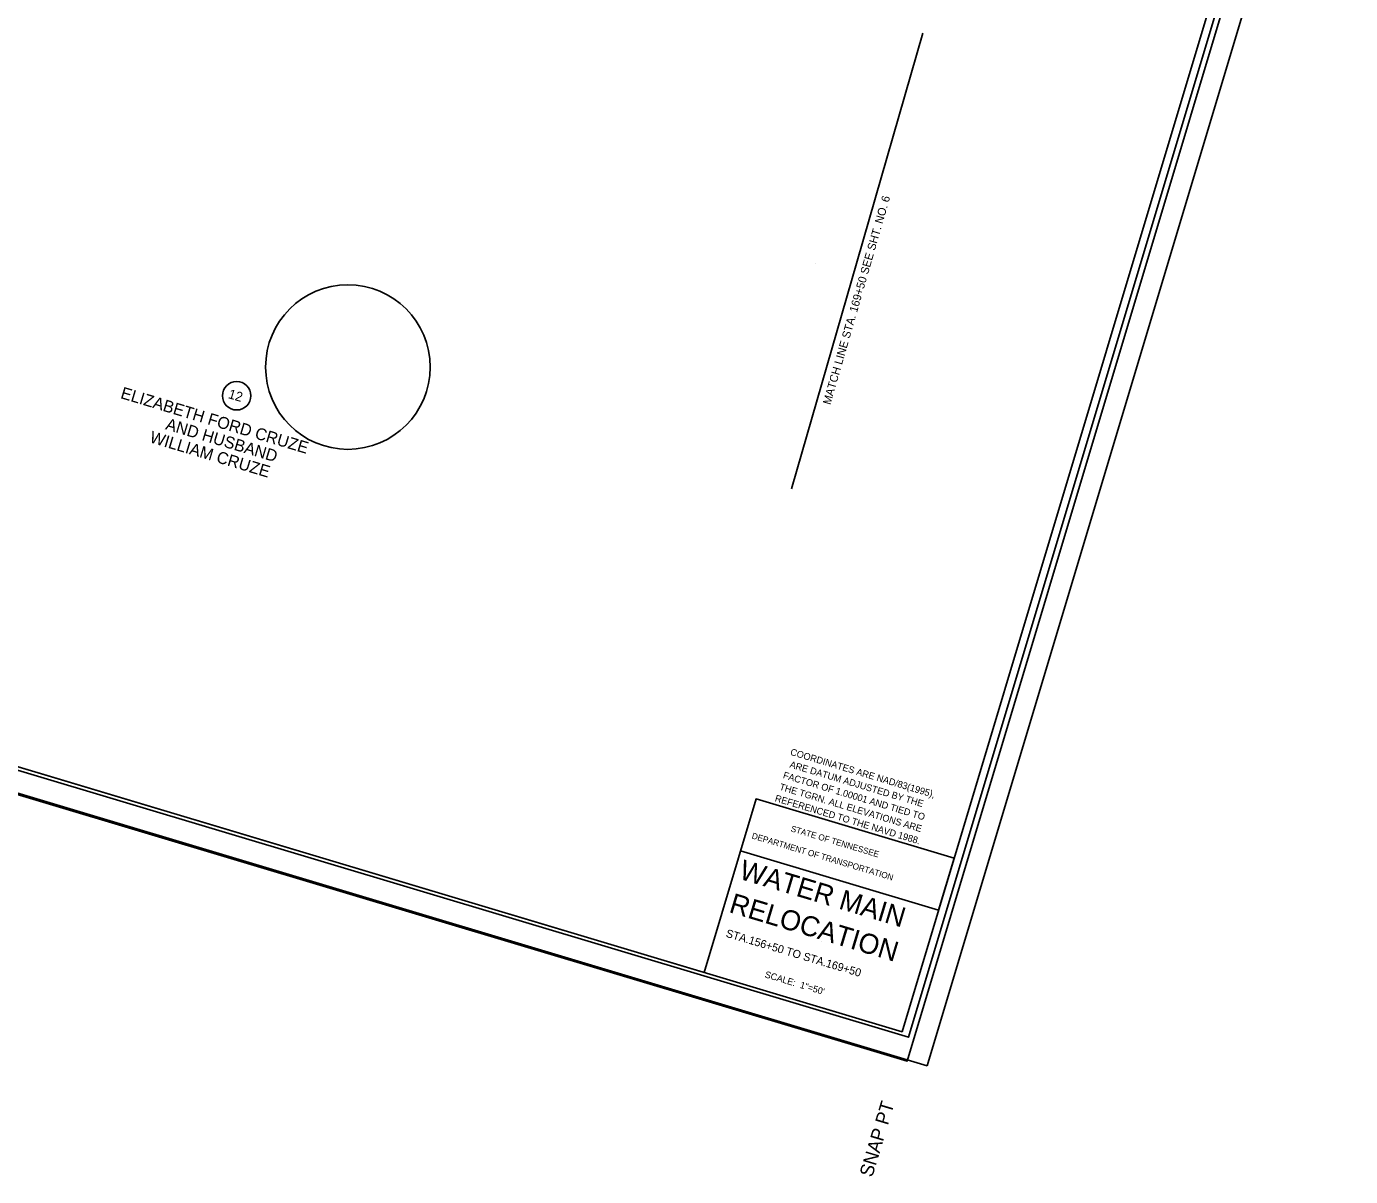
# Model space of a CAD drawing. Extents: x 2627582 to 2629622, y 568931 to 570612.
# Drawn here: x 2628642 to 2629619, y 568931 to 569779 of the extents above; entities that cross this region are included whole.
import ezdxf

# ---------------------------------------------------------------- set-up
doc = ezdxf.new("R2010")
doc.units = 0
for name, color, linetype in [('DESIGN - CENTERLINE - Proposed Text', 7, 'Continuous'), ('DESIGN - SCRATCH - User 1', 7, 'Continuous'), ('DESIGN - SHEET - Corner Text', 7, 'Continuous'), ('DESIGN - SHEET - Light Grid', 7, 'Continuous'), ('DESIGN - SHEET - Linework', 7, 'Continuous'), ('DESIGN - SHEET - Plot Shape', 7, 'Continuous'), ('SURVEY - PROJECT INFORMATION and NOTES', 7, 'Continuous'), ('SURVEY - PROPERTY - Owners', 7, 'Continuous'), ('SURVEY - PROPERTY - Tract Numbers', 7, 'Continuous')]:
    doc.layers.add(name, color=color, linetype=linetype)

msp = doc.modelspace()

# ---------------------------------------------------------------- linework, layer by layer
at = {"layer": 'DESIGN - CENTERLINE - Proposed Text'}
msp.add_lwpolyline([(2629206.17, 569438.02), (2629254.54, 569606.2), (2629302.91, 569774.39)], dxfattribs=at)
at = {"layer": 'DESIGN - SCRATCH - User 1'}
for p, q in [((2629223.72, 569604.66), (2629223.72, 569604.66)), ((2629228.13, 569104.12), (2629228.13, 569104.12))]:
    msp.add_line(p, q, dxfattribs=at)
at = {"layer": 'DESIGN - SHEET - Light Grid'}
msp.add_lwpolyline([(2627697.64, 569511.43), (2629292.52, 569033.35), (2629595.46, 570043.92), (2628000.57, 570522.01)], close=True, dxfattribs=at)
at = {"layer": 'DESIGN - SHEET - Linework'}
for p in [(2629618.55, 570053.91), (2627582.11, 569529.15)]:
    msp.add_line(p, (2629306.31, 569012.3), dxfattribs=at)
for points in [[(2628081.32, 570495.19), (2627779.83, 569489.41), (2629287.73, 569037.39), (2629589.23, 570043.18), (2628081.32, 570495.19)], [(2629141.66, 569081.18), (2629180.03, 569209.2), (2629326.11, 569165.42), (2629314.62, 569127.1), (2629168.55, 569170.89)]]:
    msp.add_lwpolyline(points, dxfattribs=at)
at = {"layer": 'DESIGN - SHEET - Plot Shape'}
for points in [[(2627975.91, 570547.35), (2629604.32, 570059.22), (2629291.51, 569015.7), (2627663.1, 569503.83)], [(2627999.85, 570519.61), (2629589.23, 570043.18), (2629287.73, 569037.39), (2627698.36, 569513.83)]]:
    msp.add_lwpolyline(points, close=True, dxfattribs=at)
at = {"layer": 'SURVEY - PROJECT INFORMATION and NOTES'}
msp.add_circle((2628878.84, 569527.91), 60.7, dxfattribs=at)
at = {"layer": 'SURVEY - PROPERTY - Tract Numbers'}
msp.add_circle((2628796.81, 569506.74), 10.5, dxfattribs=at)

# ---------------------------------------------------------------- texts
at = {"layer": 'DESIGN - CENTERLINE - Proposed Text'}
msp.add_text('MATCH LINE STA. 169+50 SEE SHT. NO. 6', height=6, rotation=73.95539, dxfattribs=at).set_placement((2629234.84, 569499.71))
at = {"layer": 'DESIGN - SHEET - Corner Text'}
for s, height, rotation, p in [('COORDINATES ARE NAD/83(1995),', 5.0001, 343.31329, (2629204.81, 569241.81)), ('ARE DATUM ADJUSTED BY THE', 5.0001, 343.31329, (2629204.38, 569232.55)), ('THE TGRN. ALL ELEVATIONS ARE', 5.0001, 343.31329, (2629196.82, 569216.02)), ('FACTOR OF 1.00001 AND TIED TO', 5.0001, 343.31329, (2629199.47, 569224.62)), ('REFERENCED TO THE NAVD 1988.', 5.0001, 343.31329, (2629193.49, 569207.62)), ('DEPARTMENT OF TRANSPORTATION', 4.5, 343.31329, (2629176.43, 569180.11)), ('STATE OF TENNESSEE', 4.5, 343.31329, (2629205.25, 569185.36)), ('WATER MAIN ', 14.7636, 343.31329, (2629166.72, 569150.47)), ('RELOCATION', 14.764, 343.31329, (2629159.32, 569125.79)), ('STA.156+50 TO STA.169+50', 5.9055, 343.31329, (2629157.26, 569107.55)), ('SCALE:  1"=50\'', 4.9215, 343.31329, (2629186.02, 569077.6)), ('SNAP PT  ', 10, 73.31329, (2629265.67, 568929.49))]:
    msp.add_text(s, height=height, rotation=rotation, dxfattribs=at).set_placement(p)
at = {"layer": 'SURVEY - PROPERTY - Owners'}
for s, p in [('ELIZABETH FORD CRUZE', (2628710.57, 569505.09)), ('AND HUSBAND', (2628743.75, 569482.09)), ('WILLIAM CRUZE', (2628732.02, 569472.56))]:
    msp.add_text(s, height=8.75, rotation=343.31329, dxfattribs=at).set_placement(p)
at = {"layer": 'SURVEY - PROPERTY - Tract Numbers'}
msp.add_text('12', height=7, rotation=343.31329, dxfattribs=at).set_placement((2628790.06, 569505.11))

doc.saveas('drawing.dxf')
